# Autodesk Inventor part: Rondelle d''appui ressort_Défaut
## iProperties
Shininess: 64.0
Length Units: 11269
Angle Units: 11279
Time Units: 11290
Mass Units: 11283
Length Display Precision: 3
Angle Display Precision: 2
Compacted: True
Part Number: Rondelle d''appui ressort_Défaut
Document SubType Name: Modeling
Created: 2006-01
Material: Par défaut
Designer: riri
Density: 0.0
Volumn: 0.0
Area: 0.0
PropertySet Name: Model Information
Control State: 0
Master: False
Checked Out: False
Author: riri
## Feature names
1. Base1
